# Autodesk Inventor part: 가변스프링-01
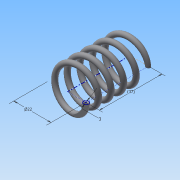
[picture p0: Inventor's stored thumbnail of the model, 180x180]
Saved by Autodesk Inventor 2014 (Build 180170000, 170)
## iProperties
Created: 2015-09
Part Number: 가변스프링-01
Material: 강철, 탄소
Document SubType Name: Modeling
Designer: study
Density: 7.87 g/cm^3
Appearance: 반연마
Mass: 18.9154 g
Surface Area: 32.5802 cm^2
Volume: 2.40348 cm^3
Author: study
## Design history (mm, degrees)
sketch "스케치1"
  geometry: L1 (0, 0)-(11, 0); L2 (11, 0)-(11, 40.095); L3 (11, 40.095)-(0, 40.095); L4 (0, 40.095)-(0, 0); C1 r 1.5 at (11, 0)
  constraints: 8 end point, 2 parallel, 1 centre point, 1 coincident, 1 horizontal, 1 perpendicular
  dimensions: "d0" = 22 diameter of L2 L4; "d1" = 3 diameter of C1; "d2" = 40.0955 distance of L1.end L2.end (derived)
feature "코일1" sketch "스케치1" pitch "d3" = 10; turns "d5" = 5; dims "d4" = 40.0955 (= d2), "d6" = 0, angle "d7" = 90 deg, angle "d8" = 90 deg, "d9" = 0, "d10" = 0
sketch "스케치2"
  geometry: L1 (-12.5, 0)-(-9.5, 0) reference; 1 further point
  constraints: 1 horizontal alignment
extrude "돌출1" cut sketch "스케치2" stored distance "d11" = 10; taper "d12" = 0 deg
node "작업 평면1"
sketch "스케치3"
  geometry: L1 (-9.5, 0)-(-12.5, 0) reference; 1 further point
  constraints: 1 horizontal alignment
extrude "돌출2" cut sketch "스케치3" stored distance "d14" = 10; taper "d15" = 0 deg
node "솔리드1"
node "절단 모서리 투영1"
node "절단 모서리 투영2"
other parameters: "d13" = 40.0955 (= d2)
